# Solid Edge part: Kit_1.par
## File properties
Sűrűség: 0,000 kg/m^3
Pontosság: 0,990
Author: bmolnar
Last saved by: bmolnar
Revision: 77
Username: bmolnar
Dokumentum tartalom típus: 0
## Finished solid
Body 1: solid body, 43 faces, 60 edges, 50 vertices.
  Faces by surface: cylinder 15, cone 12, plane 12, torus 4
  Edges by curve: circle 46, line 14
Bounding box of the edges (mm; curved faces can reach further): 106.000 x 105.975 x 9.950, from (-53, -50.85, 95.1) to (53, 55.125, 105.05).
Cylindrical faces by radius (mm): R1.75 x2, R3.5 x4, R12.8 x1, R13.45 x1, R14 x1, R14.9 x1, R15 x1, R40 x1, R46.625 x1, R50.85 x1, R53 x1
Conical faces (half-angle, radius in mm at the cone's reference point): 3 deg R14.95 x1, 7 deg R14.2695 x1, 14 deg R12.65 x1, 14 deg R13.057 x1, 17 deg R12.65 x1, 23 deg R13.4211 x1, 42.5 deg R12.637 x1, 45 deg R13.7 x1, 45 deg R39.5 x1, 84 deg R13.012 x1, 85 deg R14.6625 x1, 87 deg R12.7157 x1
Toroidal faces (ring radius, tube radius in mm): R13.4008 r0.225 x1, R13.8914 r0.325 x1, R14.7 r0.2 x1, R40.8 r0.8 x1
Planar faces by outward normal: +z 7, -z 3, oblique 2
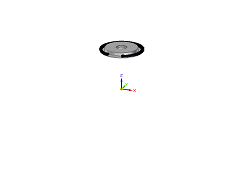
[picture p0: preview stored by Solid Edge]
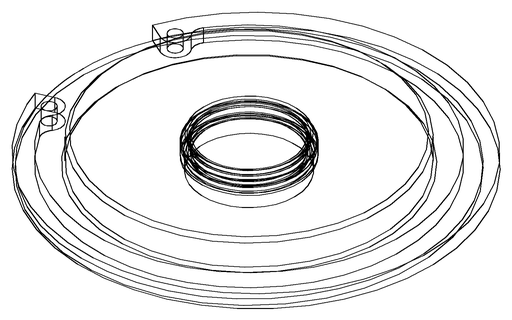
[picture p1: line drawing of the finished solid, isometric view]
